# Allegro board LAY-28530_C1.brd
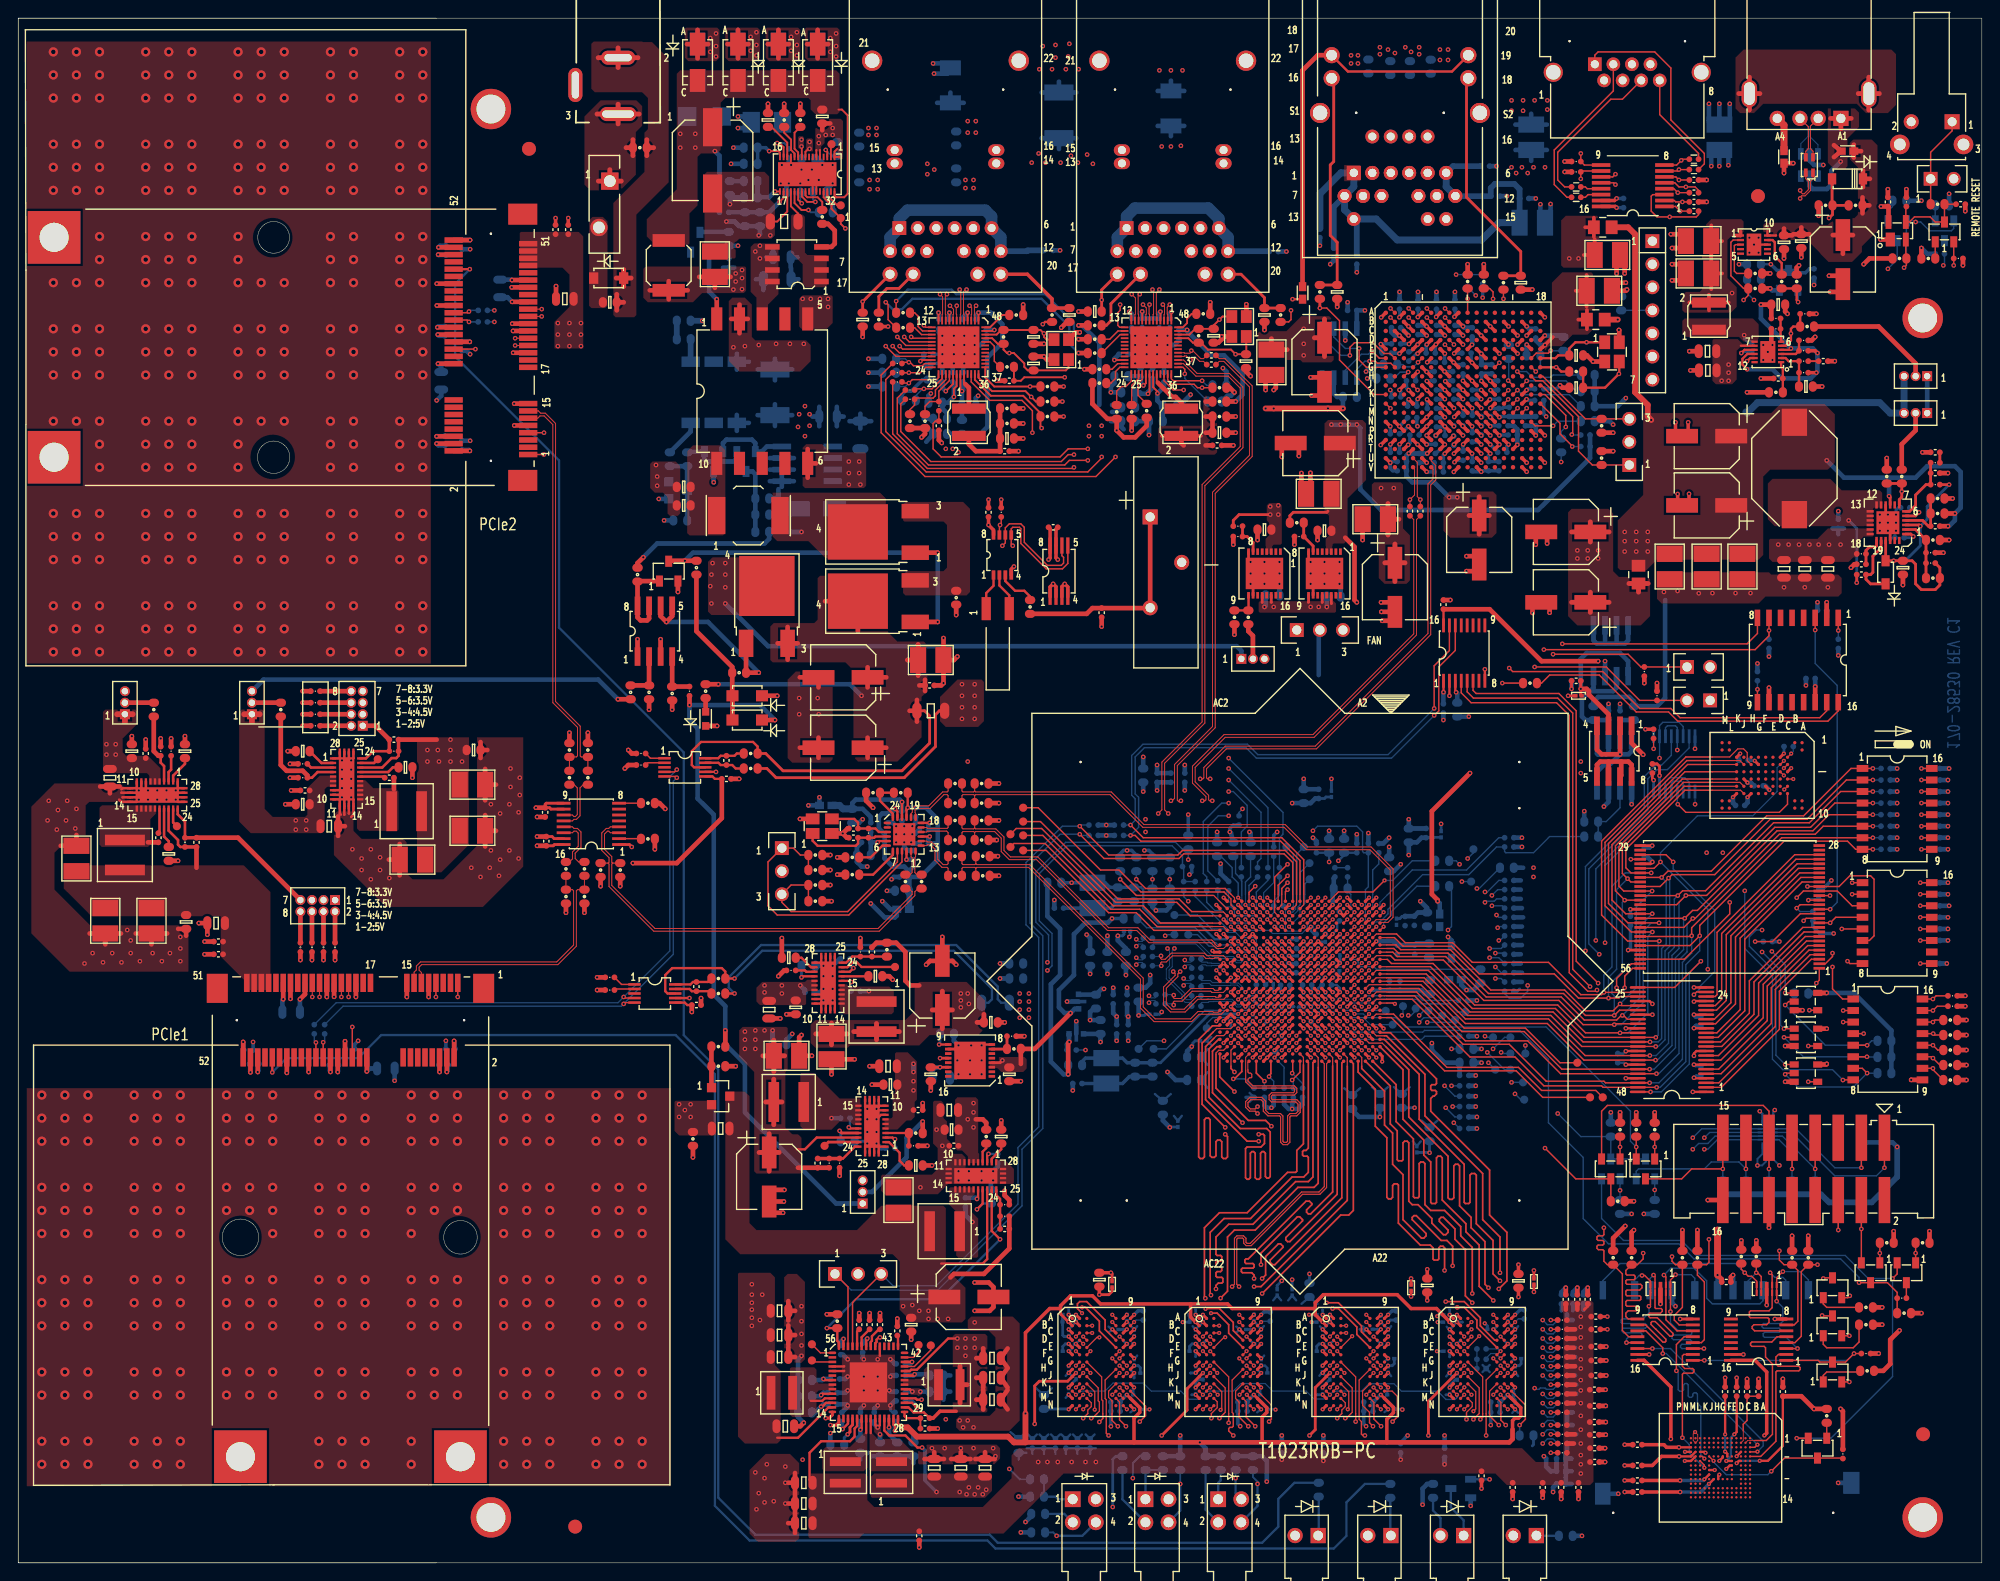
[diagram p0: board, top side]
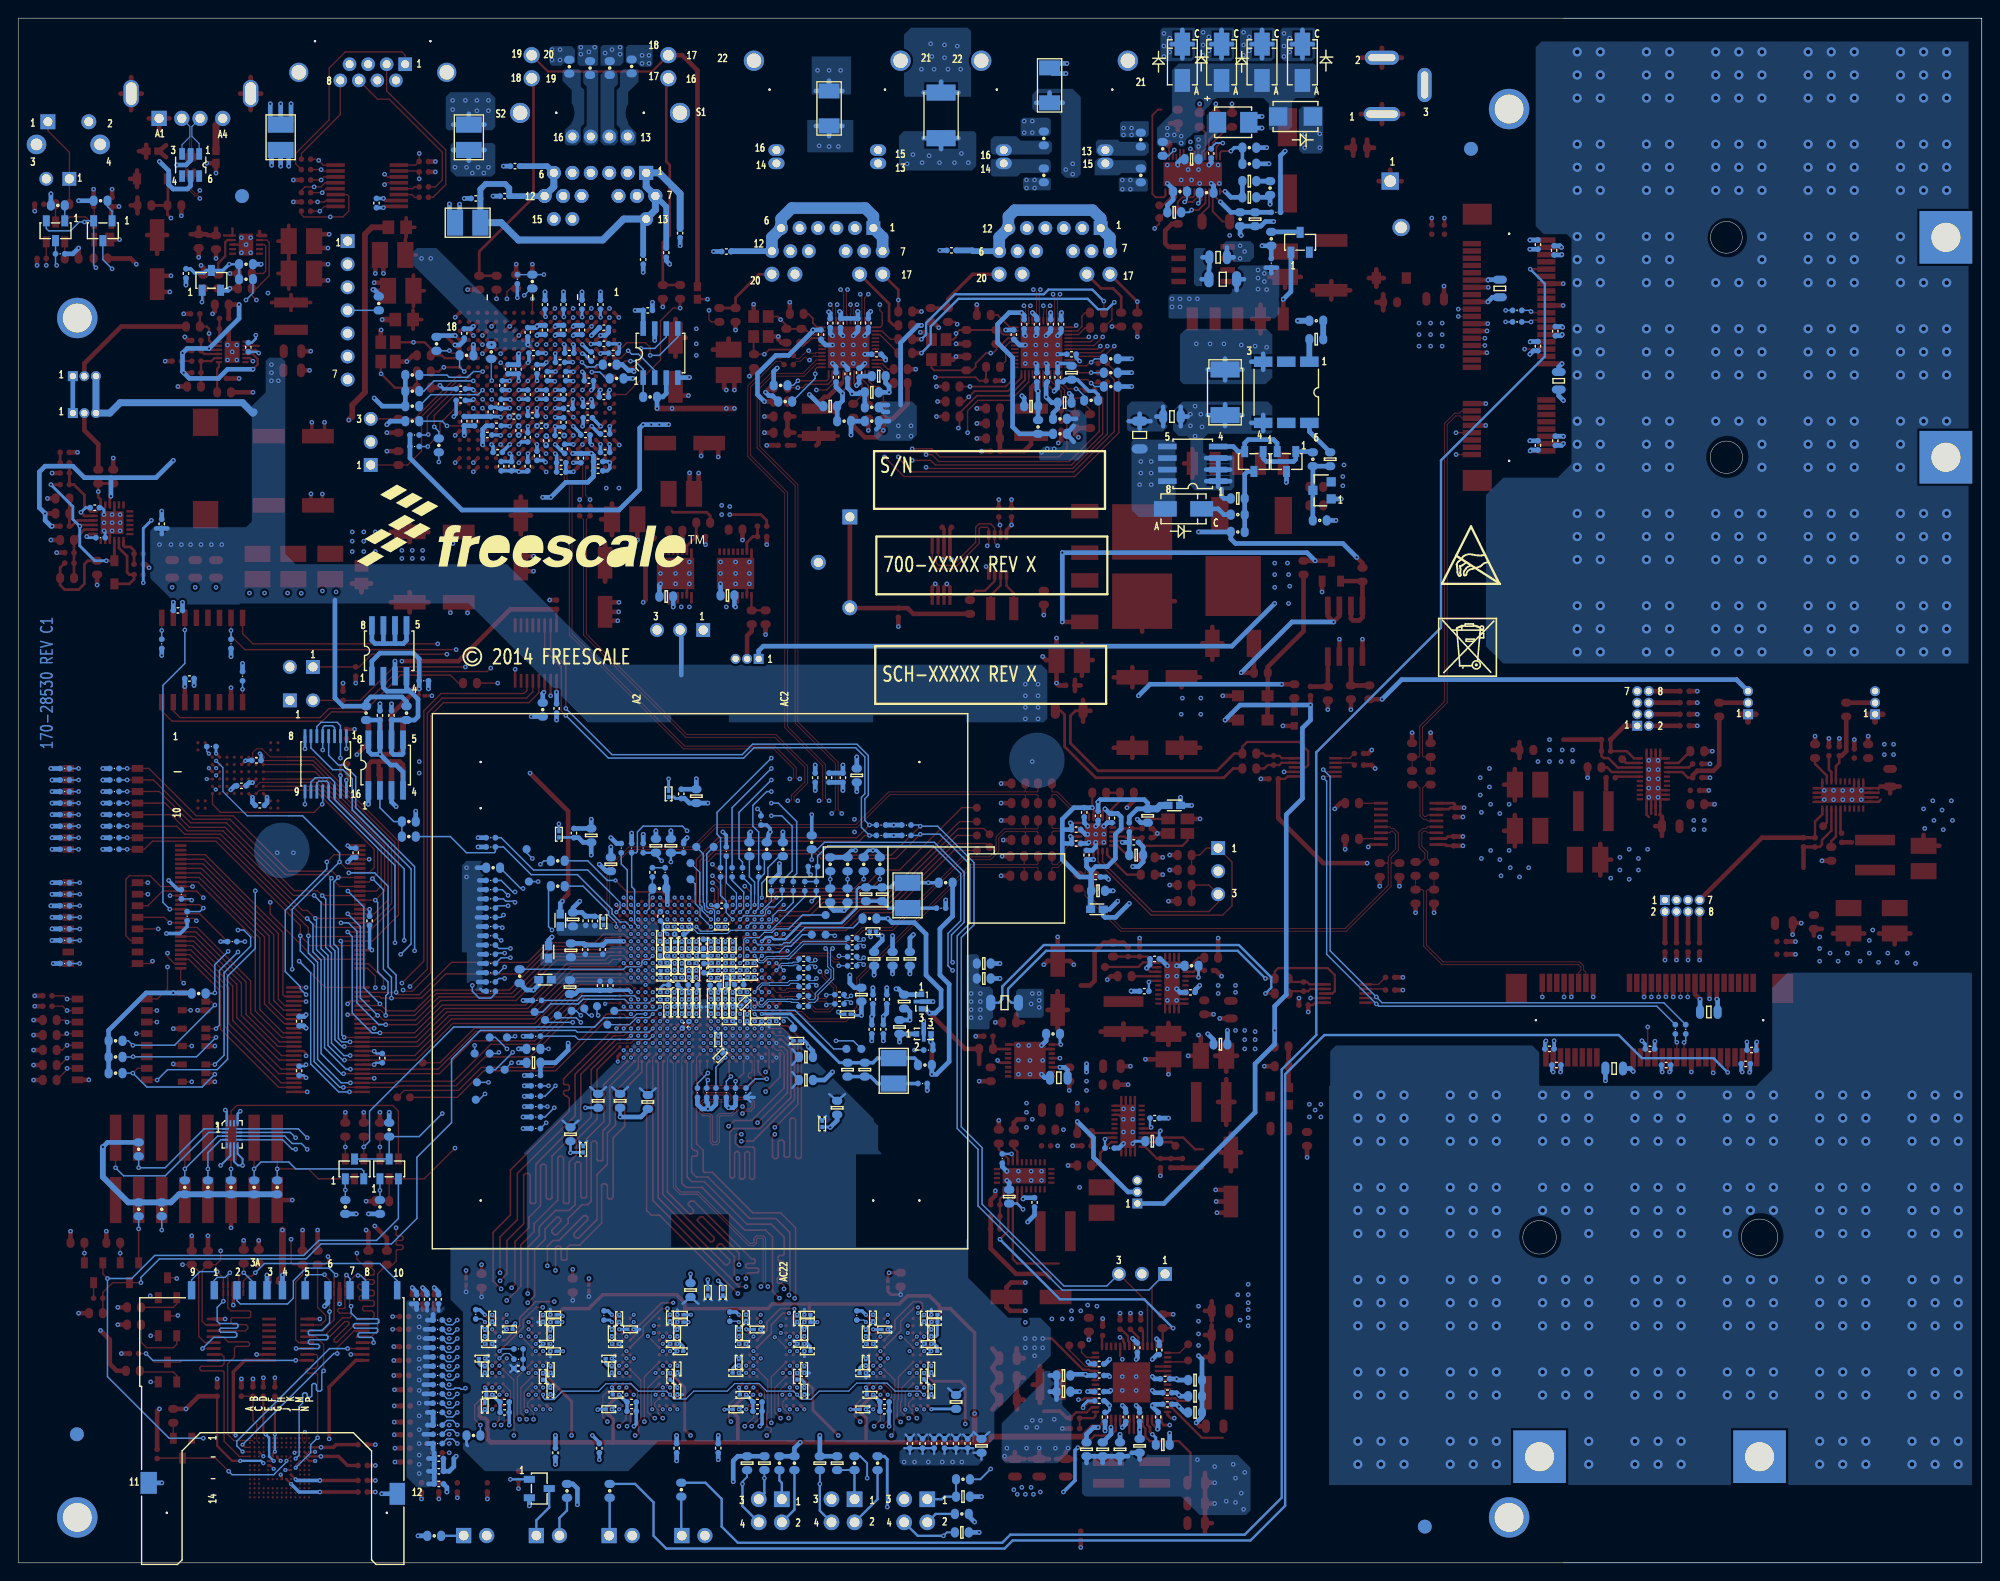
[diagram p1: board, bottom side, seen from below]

Outline 216 x 170 mm; copper layers: TOP, L2_GND, L3_INT1, L4_INT2, L5_PWR, BOTTOM. Coordinates in mm from the lower left corner of the outline.
Outline path: circle c24.45,35.83 r2 ; circle c28.1,145.88 r1.75 ; circle c28.1,121.68 r1.78 ; circle c48.65,35.83 r1.84 ; 0,170 0,0 216,0 216,170 46,170 ; 0,170 0,0 1,0 46,0 ; 0,170 1,170 46,170 ; 0,170 46,170

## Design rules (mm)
net group 2.5G-CMP: nets 2.5G_CMP_N 2.5G_CMP_P
net group 2.5GMDI0: nets 2.5G_MDI0_N 2.5G_MDI0_P
net group 2.5GMDI1: nets 2.5G_MDI1_N 2.5G_MDI1_P
net group 2.5GMDI3: nets 2.5G_MDI3_N 2.5G_MDI3_P
net group 2.5MDI2: nets 2.5G_MDI2_N 2.5G_MDI2_P
net group EC1--MDI2: nets EC1_MDIN2 EC1_MDIP2
net group EC1-MDI0: nets EC1_MDIN0 EC1_MDIP0
net group EC1-MDI1: nets EC1_MDIN1 EC1_MDIP1
net group EC1-MDI3: nets EC1_MDIN3 EC1_MDIP3
net group EC1_RXC: nets EC1_RXC EC1_RXC/PHYAD1
net group EC1_RXCTL: nets EC1_RXCTL EC1_RXCTL/PHYAD2
net group EC1_RXD1: nets EC1_RXD1 EC1_RXD1/CFG_MODE0
net group EC1_RXD2: nets EC1_RXD2 EC1_RXD2/CFG_MODE1
net group EC1_RXD3: nets EC1_RXD3 EC1_RXD3/CFG_MODE2
net group EC1_TXC: nets EC1_TXC N24320726
net group EC1_TXCTL: nets EC1_TXCTL N24320723
net group EC1_TXD0: nets EC1_TXD0 N24320797
net group EC1_TXD1: nets EC1_TXD1 N24320800
net group EC1_TXD2: nets EC1_TXD2 N24320803
net group EC1_TXD3: nets EC1_TXD3 N24320806
net group EC1_VDDREG: nets EC1_VDDREG N24288324
net group I2C1_SCL: nets I2C1_SCL N26621044
net group I2C1_SDA: nets I2C1_SDA N26621047
net group I2C2_SCL: nets I2C2_SCL N26620998
net group I2C2_SDA: nets I2C2_SDA N26621001
net group LANEA_RX_N: nets LANEA_RX_N N24582200
net group LANEA_RX_P: nets LANEA_RX_P N24582130
net group LANEA_TX_N: nets LANEA_TX_N N24582286
net group LANEA_TX_P: nets LANEA_TX_P N24582275
net group LANEB_RX_N: nets LANEB_RX_N N24582194
net group LANEB_RX_P: nets LANEB_RX_P N24582197
net group LANEB_TX_N: nets LANEB_TX_N N24185672
net group LANEB_TX_P: nets LANEB_TX_P N24185665
net group LANEC_RX_N: nets LANEC_RX_N N25115912
net group LANEC_RX_P: nets LANEC_RX_P N25115909
net group LANEC_TX_N: nets LANEC_TX_N N24582369
net group LANEC_TX_P: nets LANEC_TX_P N24582387
net group LANED_RX_N: nets LANED_RX_N N24307585
net group LANED_RX_P: nets LANED_RX_P N24307470
net group LANED_TX_N: nets LANED_TX_N N25116018
net group LANED_TX_P: nets LANED_TX_P N25116015
net group LED_G-: nets AQR_LED_GRN LED_G-
net group LED_Y-: nets AQR_LED_YEL LED_Y-
net group MPCIE1_CLK+: nets MPCIE1_CLK+ N24164587
net group MPCIE1_CLK-: nets MPCIE1_CLK- N24164590
net group MPCIE2_CLK+: nets MPCIE2_CLK+ N24164581
net group MPCIE2_CLK-: nets MPCIE2_CLK- N24164584
net group N23886021: nets N23886021 N23886023
net group N23886074: nets N23886069 N23886074
net group N24107203: nets N24107203 N24936812
net group N24107950: nets N24107950 N24108405
net group N24145679: nets N24145679 N24157795
net group N24145732: nets N24145732 N24145752
net group N24151368: nets N24151368 N24151377
net group N24158224: nets N24158107 N24158224
net group N24158233: nets N24158105 N24158233
net group N24187101: nets N24187101 N24616249
net group N24291582: nets N24291582 N24291591
net group N24302493: nets N24302493 N24302533
net group N24378650: nets N24378635 N24378650
net group N24379174: nets N24379174 N24380394
net group N24392141: nets N24392141 N25440106
net group N24480366: nets N24480366 N26683109
net group N24506911: nets N24506911 N24515056
net group N24509767: nets N24509767 N24509789
net group N24551325: nets N24551325 N24551347
net group N24994453: nets N24994453 N26682338
net group N25032157: nets N24389900 N25032157
net group N25157716: nets N25157716 N25157741
net group N25157815: nets N25157671 N25157815
net group N25169246: nets N24379631 N25169246
net group N26607524: nets N26607524 N26607860
net group N26607549: nets N26607549 N26607619
net group N26669831: nets N26669831 N26683821
net group N26901158: nets N26901158 N26901371
net group NUART_RTS: nets NUART_RTS RS232_RTS0
net group RS232_CTS0: nets NUART_CTS RS232_CTS0
net group RS232_RXD0: nets RS232_RXD0 UART_SIN
net group SD_CLK1_N: nets N24158001 SD_CLK1_N
net group SD_CLK1_P: nets N24158003 SD_CLK1_P
net group SD_CLK2_N: nets N24158103 SD_CLK2_N
net group SD_CLK2_P: nets N24158101 SD_CLK2_P
net group SDHC_VS: nets N24675233 SDHC_VS
net group SGMII-MDI0: nets SGMII_MDIN0 SGMII_MDIP0
net group SGMII-MDI1: nets SGMII_MDIN1 SGMII_MDIP1
net group SGMII-MDI2: nets SGMII_MDIN2 SGMII_MDIP2
net group SGMII-MDI3: nets SGMII_MDIN3 SGMII_MDIP3
net group SYS_REFCLK_N: nets N24157991 SYS_REFCLK_N
net group SYS_REFCLK_P: nets N24157984 SYS_REFCLK_P
net group UART_SOUT: nets RS232_TXD0 UART_SOUT
net group USB1: nets N24378208 N24378216
net group USB2: nets N24378188 N24378195
net group VBAT_OPT1: nets N23887688 VBAT_OPT1
net group VR500_1V5: nets N24081686 VR500_1V5
net group 12: nets 12 N26747839 N26748165
net group 12V_DECT: nets 12V_DECT N24653996 N24678302 N25120670
net group 12V_SUP: nets 12V_SUP N24652945 N24654004
net group 34: nets 34 N26747836 N26748168
net group 56: nets 56 N26747833 N26748171
net group 78: nets 78 N26747830 N26748174
net group ADP_12V: nets ADP_12V N25696806 N26711184 N26711194
net group AQR_INT_N: nets 1V2_RST_N AQR105_VA12 AQR_INT_N EMI2_MDC EMI2_MDIO N24186507 N24186703 N24189801 N24970769
net group AVDD_SD1_PLL1: nets AVDD_SD1_PLL1 N24275030 N24275210 N24275332 N24275468 N24443017
net group DCDC_1V0_SUP: nets DCDC_1V0_SUP N24137912 N24137946 N24137962 N25622344 N25622365
net group DCDC_5V0: nets DCDC_5V0 N24480273 N24480391
net group DDR-DATA1-U1-U37: nets DDR4_DM0 DDR4_DQ0 DDR4_DQ1 DDR4_DQ2 DDR4_DQ3 DDR4_DQ4 DDR4_DQ5 DDR4_DQ6 DDR4_DQ7 DDR4_DQS0 DDR4_DQS0_N
net group DDR-DATA3-U1-U35: nets DDR4_DM2 DDR4_DQ16 DDR4_DQ17 DDR4_DQ18 DDR4_DQ19 DDR4_DQ20 DDR4_DQ21 DDR4_DQ22 DDR4_DQ23 DDR4_DQS2 DDR4_DQS2_N
net group DDR-DATA4-U1-U34: nets DDR4_DM3 DDR4_DQ24 DDR4_DQ25 DDR4_DQ26 DDR4_DQ27 DDR4_DQ28 DDR4_DQ29 DDR4_DQ30 DDR4_DQ31 DDR4_DQS3 DDR4_DQS3_N
net group DDR-DATA-UI-U36: nets DDR4_DM1 DDR4_DQ8 DDR4_DQ9 DDR4_DQ10 DDR4_DQ11 DDR4_DQ12 DDR4_DQ13 DDR4_DQ14 DDR4_DQ15 DDR4_DQS1 DDR4_DQS1_N
net group EC1_AVDD10: nets EC1_AVDD10 EC1_DVDD10 N24289313 N24289334
net group EC1_DVDD_3V3: nets EC1_DVDD_3V3 EC1_LED0/PHYAD0 EC1_LED2/CFG_LDO1 N25236971
net group EC1_DVDDRG: nets EC1_DVDDRG EC1_RXD0 N24291955
net group EC1_LED1/CFG_LDO0: nets EC1_LED1/CFG_LDO0 N24294558 N25235874
net group EMI1_MDC: nets EMI1_MDC N25171285 N25171337
net group EMI1_MDIO: nets EMI1_MDIO N25171340 N25276538
net group GND_SIGNAL: nets GND_SIGNAL N24105172 N24105186 N24105908 N24106035 N24106207 N24106733 N24106981 N24107357 N24108952 N24109652 N24109671 N24109742 N24109897 N24109974 N24109983 N24110294 N24932777 N24935123 N24935830 N24935853 N25029315
net group GPIO3_0_WAKE_L: nets GPIO3_0_WAKE_L N26623758 N26628373
net group INTVCC: nets INTVCC N25157944 N25158030 N25158044
net group LDO_1V0: nets LDO_1V0 N24442993 N25212963
net group N24107483: nets N24107470 N24107483 N24107486
net group N24107780: nets N24107616 N24107621 N24107780
net group N24379558: nets N24378377 N24379468 N24379558
net group N24480234: nets N24480234 N24480259 N24480399 N24480593 N24480595
net group POE_12V: nets N24107840 N24107947 N24108768 N25118599 POE_12V
net group SGMII_AVDD10: nets N24302177 N24302183 SGMII_AVDD10 SGMII_DVDD10
net group SGMII_DVDD_3V3: nets DCDC1_3V3 N24301989 N24506783 N24506809 N24506829 N25238664 SGMII_DVDD_3V3 SGMII_LED0/PHYAD0 SGMII_LED2/CFG_LDO1 SGMII_VDDREG
net group SGMII_DVDDRG: nets SGMII_DVDDRG SGMII_RXC/PHYAD1 SGMII_RXD1/CFG_MODE0 SGMII_RXD2/CFG_MODE1
net group SGMII_LED1/CFG_LDO0: nets N24303062 N25239505 SGMII_LED1/CFG_LDO0
net group VPA: nets N26669717 N26669739 N26669755 VPA
net group VPA_PCIE2: nets N26901046 N26901068 N26901080 VPA_PCIE2

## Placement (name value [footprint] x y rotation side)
BH1  Mounting Hole  [MH175-125P]  52 160 0 top
BH2  Mounting Hole  [MH175-125P]  209.5 137 0 top
BH3  Mounting Hole  [MH175-125P]  52 5 0 top
BH4  Mounting Hole  [MH175-125P]  209.5 5 0 top
BT1  WBA-3B2 U  [SKT_BAT_225X886_3V]  124.52 115.11 270 top
C1  0.1uF  [CC0603_OV]  88.45 159.18 270 top
C2  10uF  [CASE_F_8P5X8P5]  76.38 154.35 270 top
C3  0.1uF  [CC0402_25]  184.33 152.19 0 top
C4  0.1uF  [CC0402_25]  184.33 150.8 180 top
C5  0.1uF  [CC0402_25]  184.33 149.78 0 top
C6  0.1uF  [CC0402_25]  205.67 149.78 90 top
C7  0.1uF  [CC0402_25]  213.67 149.53 180 top
C8  0.1uF  [CC0402_25]  184.33 148.77 0 top
C9  100PF  [CC0603_OV]  65.08 138.73 0 top
C10  47UF  [CC1210]  184.84 145.46 180 top
C11  1000PF  [CC0603_OV]  196.14 145.46 270 top
C12  10uF  [CC0603_OV]  194.24 145.34 270 top
C13  47UF  [CC1210]  174.81 143.94 0 top
C14  100uF  [CCE63X55]  200.72 143.43 270 top
C15  47UF  [CC1210]  184.84 141.91 180 top
C16  470PF  [CC0603_OV]  165.28 140.89 270 top
C17  47UF  [CC1210]  173.92 140 0 top
C18  470PF  [CC0603_OV]  145.09 139.88 270 top
C19  4.7uF  [CC0603_OV]  193.6 138.48 180 top
C20  100PF  [CC0603_OV]  118.42 137.72 180 top
C21  2200PF  [CC1812_A]  83.24 128.83 270 bottom
C22  100PF  [CC0603_OV]  115.63 137.34 270 top
C23  100PF  [CC0603_OV]  137.09 137.34 270 top
C24  100PF  [CC0603_OV]  92.89 136.83 270 top
C25  18PF  [CC0603_OV]  131.5 135.05 270 top
C26  18PF  [CC0603_OV]  111.69 134.92 270 top
C27  470pF  [CC0805_OV]  89.08 126.16 180 bottom
C28  4.7uF  [CC0603_OV]  73.21 118.41 180 top
C29  22uF  [CC0805_OV]  185.83 133.35 180 top
C30  0.1uF  [CC0402_25]  131.25 132.89 180 top
C31  18PF  [CC0603_OV]  171.38 132.89 0 top
C32  68PF  [CC0402_25]  198.56 132.26 180 top
C33  18PF  [CC0603_OV]  135.06 132.26 270 top
C34  47UF  [CC1210]  137.85 132.13 270 top
C35  100uF  [CCE63X55]  143.69 132.13 270 top
C36  18PF  [CC0603_OV]  111.69 132 90 top
C37  0.1uF  [CC0402_25]  131.25 131.87 180 top
C38  4.7uF  [CC0603_OV]  73.21 116.38 180 top
C39  22uF  [CC0805_OV]  185.86 131.24 180 top
C40  1UF  [CC0603_OV]  81.84 117.14 0 bottom
C41  0.1uF  [CC0402_25]  193.6 130.35 180 top
C42  22PF  [CC0402_25]  109.02 130.1 180 top
C43  10PF  [CC0603_OV]  196.65 129.46 180 top
C44  18PF  [CC0603_OV]  171.38 129.33 180 top
C45  22PF  [CC0402_25]  101.28 125.14 270 top
C46  4.7uF  [CC0603_OV]  132.14 124.38 0 top
C47  100uF  [CCE63X55]  185.73 124 180 top
C48  4.7uF  [CC0603_OV]  108.77 123.75 0 top
C49  100uF  [CCE63X55]  142.68 123.24 180 top
C50  0.1uF  [CC0402_25]  131.88 122.98 180 top
C51  0.1uF  [CC0402_25]  108.51 122.35 180 top
C52  220pF  [CC0402_25]  210.88 122.22 180 top
C53  10pF  [CC0402_25]  210.88 119.94 0 top
C54  47UF  [CC1210]  143.06 117.65 180 top
C55  100uF  [CCE63X55]  185.73 116.38 180 top
C56  0.1uF  [CC0402_25]  153.09 115.75 90 top
C57  0.1uF  [CC0402_25]  154.23 115.75 90 top
C58  47UF  [CC1210]  149.28 114.86 180 top
C59  100UF  [CCE63X55]  90.73 97.46 180 top
C60  0.1uF  [CC0402_25]  119.18 104.57 270 top
C61  100PF  [CC0402_25]  210.88 114.09 180 top
C62  10uF  [CC0603_OV]  137.09 113.71 180 top
C63  10uF  [CC0603_OV]  143.69 113.59 180 top
C64  100uF  [CCE63X55]  170.24 113.46 180 top
C65  100uF  [CCE63X55]  160.71 112.57 270 top
C66  0.1uF  [CC0402_25]  106.74 115.62 90 top
C67  0.1uF  [CC0402_25]  202.75 109.9 180 top
C68  47UF  [CC1210]  181.67 109.65 270 top
C69  47UF  [CC1210]  185.73 109.65 270 top
C70  47UF  [CC1210]  189.67 109.65 270 top
C71  2.2uF  [CC0603_OV]  207.32 109.52 270 top
C72  22uF  [CC0805_OV]  194.24 109.4 270 top
C73  22uF  [CC0805_OV]  196.53 109.4 270 top
C74  22uF  [CC0805_OV]  199.07 109.4 270 top
C75  0.1uF  [CC0402_25]  202.75 108.76 0 top
C76  100uF  [CCE63X55]  151.44 107.36 270 top
C77  100UF  [CCE63X55]  90.73 89.71 180 top
C78  100uF  [CCE63X55]  170.24 105.71 180 top
C79  22UF  [CC1210]  100.39 99.36 0 top
C80  0.1uF  [CC0402_25]  100.26 96.57 0 top
C81  0.01UF  [CC0402_25]  171.38 97.08 180 top
C82  0.1UF  [CC0201]  171.63 95.43 180 top
C84  0.1uF  [CC0402_25]  77.91 86.28 180 top
C85  2pF  [CC0402_25]  91.88 80.82 180 top
C86  2pF  [CC0402_25]  91.88 79.8 180 top
C87  10pF  [CC0402_25]  93.91 67.23 270 top
C88  2200PF  [CC0603_OV]  84.77 66.6 180 top
C89  1UF  [CC0603_OV]  94.29 64.56 0 top
C90  100uF  [CCE63X55]  101.66 63.55 90 top
C91  10uF  [CC0603_OV]  85.53 61.14 270 top
C92  22uF  [CC0805_OV]  82.61 60.88 270 top
C93  1UF  [CC0603_OV]  106.99 59.48 0 top
C94  47UF  [CC1210]  89.46 56.82 270 top
C95  47UF  [CC1210]  84.51 55.8 0 top
C96  22uF  [CC0805_OV]  95.69 54.66 180 top
C97  10uF  [CC0603_OV]  100.39 53.77 270 top
C98  10uF  [CC0603_OV]  109.02 53.77 270 top
C99  10uF  [CC0603_OV]  95.94 52.63 180 top
C100  0.1uF  [CC0402_25]  98.99 49.83 180 top
C101  22uF  [CC0805_OV]  102.42 49.83 180 top
C102  10uF  [CC0603_OV]  102.67 47.67 180 top
C103  2200PF  [CC0603_OV]  108.13 46.91 90 top
C104  0.1uF  [CC0402_25]  102.93 45.9 0 top
C105  2200PF  [CC0603_OV]  98.74 43.74 0 top
C106  10pF  [CC0402_25]  87.94 43.99 90 top
C107  100uF  [CCE63X55]  82.61 42.47 270 top
C108  47UF  [CC1210]  96.83 39.93 90 top
C109  10pF  [CC0402_25]  108.51 36.75 180 top
C110  10uF  [CC0603_OV]  118.93 31.16 90 top
C111  10uF  [CC0603_OV]  165.03 31.04 90 top
C112  0.1UF  [CC0201]  166.73 30.96 90 top
C113  0.1uF  [CC0402_25]  187.89 30.91 0 top
C114  0.1UF  [CC0201]  120.33 30.66 90 top
C115  10uF  [CC0603_OV]  155 30.53 90 top
C116  22UF  [CC0805_OV]  84.38 15.03 0 top
C117  0.1UF  [CC0201]  153.22 30.27 90 top
C118  100uF  [CCE63X55]  104.58 29.26 0 top
C119  0.1uF  [CC0402_25]  170.24 29 90 top
C120  0.1uF  [CC0402_25]  171.51 29 90 top
C121  0.1uF  [CC0402_25]  172.65 29 90 top
C122  22UF  [CC0805_OV]  83.75 27.73 0 top
C123  0.1uF  [CC0402_25]  173.54 27.1 0 top
C124  0.22UF  [CC0402_25]  92.51 26.21 90 top
C125  1.0UF  [CC0402_25]  93.66 26.21 90 top
C126  1.0UF  [CC0402_25]  94.8 26.21 90 top
C127  1UF  [CC0603_OV]  98.23 26.21 270 top
C128  0.1uF  [CC0402_25]  173.54 25.7 0 top
C129  0.47uF  [CC0402_25]  96.7 25.52 90 top
C130  22UF  [CC0805_OV]  83.75 25.07 0 top
C131  0.1uF  [CC0402_25]  173.54 23.8 0 top
C132  22UF  [CC0805_OV]  83.75 22.65 0 top
C133  22UF  [CC0805_OV]  107.12 22.53 0 top
C134  0.1uF  [CC0402_25]  173.54 22.27 0 top
C135  0.1uF  [CC0402_25]  173.54 20.62 0 top
C136  22UF  [CC0805_OV]  107.12 20.37 0 top
C137  0.1uF  [CC0402_25]  173.38 19.05 0 top
C138  0.1uF  [CC0402_25]  187.76 18.84 90 top
C139  0.1uF  [CC0402_25]  189.03 18.84 90 top
C140  0.1uF  [CC0402_25]  190.18 18.84 90 top
C141  1UF  [CC0402_25]  191.45 18.84 90 top
C142  2.2uF  [CC0402_25]  194.11 18.84 270 top
C143  22UF  [CC0805_OV]  107.12 17.96 0 top
C144  0.1uF  [CC0402_25]  173.38 17.27 0 top
C145  0.1UF  [CC0402_25]  99.75 15.92 180 top
C146  0.1uF  [CC0402_25]  173.38 15.49 0 top
C147  0.1UF  [CC0402_25]  99.75 14.78 0 top
C148  0.1uF  [CC0402_25]  173.38 14.1 0 top
C149  1UF  [CC0402_25]  178.11 13 180 top
C150  0.1uF  [CC0402_25]  173.41 12.62 0 top
C151  0.1uF  [CC0402_25]  173.41 11.1 0 top
C152  0.1uF  [CC0402_25]  178.11 10.72 180 top
C153  22UF  [CC0805_OV]  100.77 10.46 90 top
C154  22UF  [CC0805_OV]  103.69 10.46 90 top
C155  22UF  [CC0805_OV]  106.36 10.46 90 top
C156  0.1uF  [CC0402_25]  160.97 9.57 270 top
C157  0.1uF  [CC0402_25]  178.11 9.07 180 top
C158  22UF  [CC0805_OV]  86.42 8.81 180 top
C159  0.1uF  [CC0402_25]  164.39 8.3 270 top
C160  0.1uF  [CC0402_25]  167.7 8.3 270 top
C161  0.1uF  [CC0402_25]  169.73 8.3 270 top
C162  0.1uF  [CC0402_25]  171.63 8.3 270 top
C163  2.2uF  [CC0402_25]  178.11 7.8 0 top
C164  22UF  [CC0805_OV]  86.42 6.53 180 top
C165  22UF  [CC0805_OV]  86.42 4.37 180 top
C166  0.1uF  [CC0402_25]  99.12 2.97 270 top
C167  1000pF  [CC1808_A]  102.55 162.61 90 bottom
C168  1000pF  [CC1808_A]  126.8 160.07 90 bottom
C169  0.1uF  [CC1812]  114.48 159.31 90 bottom
C170  22uF  [CC3528-21]  82.35 158.54 180 bottom
C171  1000pf  [CC1210]  187.13 156.89 90 bottom
C172  1000pf  [CC1210]  166.43 156.89 90 bottom
C173  33PF  [CC0402_25]  84.77 155.12 270 bottom
C174  33PF  [CC0603_OV]  82.48 158.8 90 top
C175  1UF  [CC0603_OV]  86.92 154.48 0 bottom
C176  2.2uF  [CC0402_25]  161.35 153.72 180 bottom
C177  4700PF  [CC0603_OV]  80.57 152.07 0 bottom
C178  1000PF  [CC0603_OV]  80.57 150.29 0 bottom
C179  2.2uF  [CC0402_25]  162.49 150.42 180 bottom
C180  620pF  [CC0402_25]  165.66 150.16 0 bottom
C181  1UF  [CC0603_OV]  79.94 147.88 270 bottom
C182  0.1uF  [CC0402_25]  176.59 149.65 270 bottom
C183  2.2uF  [CC1210]  76.64 142.92 90 top
C184  0.1uF  [CC0603_OV]  88.83 148.64 0 bottom
C185  47UF  [CC1210]  166.55 147.5 0 bottom
C186  47pF  [CC0805_OV]  84 143.69 180 bottom
C187  2.2uF  [CC0402_25]  143.19 146.35 90 bottom
C188  1UF  [CC0603_OV]  73.21 134.67 0 bottom
C189  0.01UF  [CC0402_25]  113.34 144.45 0 bottom
C190  0.01UF  [CC0402_25]  138.11 144.32 0 bottom
C191  2.2uF  [CC0402_25]  144.71 144.19 90 bottom
C192  2.2uF  [CC0402_25]  147.25 143.43 90 bottom
C193  0.1uF  [CC0402_25]  197.54 141.91 90 bottom
C194  2.2uF  [CC0402_25]  158.04 138.48 270 bottom
C195  2.2uF  [CC0402_25]  156.01 138.48 270 bottom
C196  2.2uF  [CC0402_25]  153.98 138.48 270 bottom
C197  2.2uF  [CC0402_25]  151.95 138.48 270 bottom
C198  1UF  [CC0402_25]  146.74 137.84 180 bottom
C199  0.1uF  [CC0402_25]  125.53 136.45 90 bottom
C200  0.1uF  [CC0402_25]  123.63 136.45 90 bottom
C201  0.1uF  [CC0402_25]  122.48 136.45 90 bottom
C202  0.1uF  [CC0402_25]  126.68 136.45 90 bottom
C203  0.1uF  [CC0402_25]  105.34 136.32 90 bottom
C204  0.1uF  [CC0402_25]  103.94 136.32 90 bottom
C205  0.1uF  [CC0402_25]  102.42 136.32 90 bottom
C206  0.1uF  [CC0402_25]  101.28 136.32 90 bottom
C207  2.2uF  [CC0402_25]  151.57 135.94 0 bottom
C208  2200PF  [CC0603_OV]  71.68 121.46 270 bottom
C209  2.2uF  [CC0402_25]  158.04 135.68 270 bottom
C210  2.2uF  [CC0402_25]  156.01 135.68 270 bottom
C211  2.2uF  [CC0402_25]  153.98 135.68 270 bottom
C212  2.2uF  [CC0402_25]  159.95 135.43 270 bottom
C213  2.2uF  [CC0402_25]  166.93 135.3 270 bottom
C214  0.1uF  [CC0402_25]  127.69 135.18 90 bottom
C215  0.1uF  [CC0402_25]  106.48 135.18 90 bottom
C216  2.2uF  [CC0402_25]  151.57 134.16 0 bottom
C217  0.1uF  [CC0402_25]  190.68 133.78 270 bottom
C218  0.1uF  [CC0402_25]  150.55 133.14 0 bottom
C219  2.2uF  [CC0402_25]  159.31 133.14 180 bottom
C220  2.2uF  [CC0402_25]  155.38 133.14 180 bottom
C221  0.1uF  [CC0402_25]  121.6 133.02 180 bottom
C222  0.1uF  [CC0402_25]  100.13 133.02 180 bottom
C223  2.2uF  [CC0402_25]  152.96 132.76 270 bottom
C224  2.2uF  [CC0402_25]  156.39 132.13 0 bottom
C225  2.2uF  [CC0402_25]  162.11 131.37 270 bottom
C226  2.2uF  [CC0402_25]  160.97 131.37 270 bottom
C227  2.2uF  [CC0402_25]  158.93 131.37 270 bottom
C228  0.1uF  [CC0402_25]  123.5 130.99 270 bottom
C229  4.7uF  [CC0603_OV]  100.13 130.99 90 bottom
C230  0.1uF  [CC0402_25]  124.77 130.86 270 bottom
C231  2.2uF  [CC0402_25]  157.79 130.6 270 bottom
C232  2.2uF  [CC0402_25]  155.76 130.6 270 bottom
C233  4.7uF  [CC0603_OV]  121.34 130.6 180 bottom
C234  0.1uF  [CC0402_25]  126.04 130.48 270 bottom
C235  0.1uF  [CC0402_25]  103.94 130.48 270 bottom
C236  0.1uF  [CC0402_25]  102.8 130.48 270 bottom
C237  0.1uF  [CC0402_25]  101.66 130.48 270 bottom
C238  0.1uF  [CC0402_25]  153.22 130.1 180 bottom
C239  2.2uF  [CC0402_25]  162.74 129.59 270 bottom
C240  0.1uF  [CC0402_25]  167.32 129.21 180 bottom
C241  4.7uF  [CC0603_OV]  122.1 128.83 180 bottom
C242  2.2uF  [CC0402_25]  159.95 128.57 270 bottom
C243  2.2uF  [CC0402_25]  157.92 128.57 270 bottom
C244  2.2uF  [CC0402_25]  156.01 128.57 270 bottom
C245  0.1uF  [CC0402_25]  151.57 128.32 0 bottom
C246  0.1uF  [CC0402_25]  167.32 127.94 180 bottom
C247  4.7uF  [CC0603_OV]  100.89 127.68 180 bottom
C248  2.2uF  [CC0402_25]  162.87 127.56 90 bottom
C249  2.2uF  [CC0402_25]  153.35 127.3 0 bottom
C250  4.7uF  [CC0603_OV]  126.68 127.3 0 bottom
C251  4.7uF  [CC0603_OV]  104.58 127.3 0 bottom
C252  2.2uF  [CC0402_25]  155.5 127.05 180 bottom
C253  2.2uF  [CC0402_25]  164.01 126.67 270 bottom
C254  2.2uF  [CC0402_25]  159.44 126.29 0 bottom
C255  2.2uF  [CC0402_25]  161.47 126.16 180 bottom
C256  2.2uF  [CC0402_25]  153.35 126.03 0 bottom
C257  2.2uF  [CC0402_25]  166.93 125.65 90 bottom
C258  2.2uF  [CC0402_25]  165.79 125.65 90 bottom
C259  2.2uF  [CC0402_25]  156.01 125.52 90 bottom
C260  2.2uF  [CC0402_25]  163.38 125.14 180 bottom
C261  2.2uF  [CC0402_25]  158.43 125.14 180 bottom
C262  2.2uF  [CC0402_25]  160.97 124.64 270 bottom
C263  2.2uF  [CC0402_25]  151.44 124.25 0 bottom
C264  2.2uF  [CC0402_25]  164.39 124.13 180 bottom
C265  2.2uF  [CC0402_25]  153.6 124.13 0 bottom
C266  2.2uF  [CC0402_25]  156.44 124.08 180 bottom
C267  2.2uF  [CC0402_25]  159.95 123.87 90 bottom
C268  2.2uF  [CC0402_25]  157.92 123.49 90 bottom
C269  0.01UF  [CC0402_25]  155.89 122.6 270 bottom
C270  2.2uF  [CC0402_25]  163.25 122.22 180 bottom
C271  2.2uF  [CC0402_25]  151.44 122.22 0 bottom
C272  2.2uF  [CC0402_25]  158.93 121.84 90 bottom
C273  0.01UF  [CC0402_25]  154.11 121.59 270 bottom
C274  0.01UF  [CC0402_25]  152.2 121.21 180 bottom
C275  0.01UF  [CC0402_25]  156.27 121.08 180 bottom
C276  0.1uF  [CC0402_25]  162.87 120.7 90 bottom
C277  0.01UF  [CC0402_25]  161.73 120.7 270 bottom
C278  0.01UF  [CC0402_25]  159.95 120.7 270 bottom
C279  0.1uF  [CC0402_25]  152.2 120.19 0 bottom
C280  0.1uF  [CC0402_25]  156.27 120.06 0 bottom
C281  0.1uF  [CC0402_25]  207.57 116.13 180 bottom
C282  0.1uF  [CC0402_25]  200.21 114.35 90 bottom
C283  10uF  [CC0603_OV]  137.98 106.47 0 bottom
C284  10uF  [CC0603_OV]  144.71 106.35 0 bottom
C285  0.1uF  [CC0402_25]  198.43 104.82 180 bottom
C286  0.1uF  [CC0402_25]  113.85 113.97 0 top
C287  0.1uF  [CC0402_25]  197.16 97.33 180 bottom
C288  0.01UF  [CC0402_25]  176.21 93.27 270 bottom
C289  0.01UF  [CC0402_25]  174.94 93.27 270 bottom
C290  0.1uF  [CC0402_25]  189.79 88.31 180 bottom
C292  10uF  [CC0603_OV]  123.75 86.66 90 bottom
C293  0.01UF  [CC0402_25]  128.33 86.41 90 bottom
C294  0.1uF  [CC0402_25]  126.8 86.41 90 bottom
C295  0.1uF  [CC0402_25]  125.28 86.41 90 bottom
C296  0.1uF  [CC0402_25]  191.45 85.52 0 bottom
C297  0.1UF  [CC0201]  144.46 84.63 90 bottom
C298  0.01UF  [CC0402_25]  143.06 84.63 90 bottom
C299  10uF  [CC0603_OV]  141.41 84.38 90 bottom
C300  22UF  [CC0805_OV]  30.03 60.63 0 bottom
C301  0.1uF  [CC0402_25]  189.41 83.36 180 bottom
C302  0.1uF  [CC0402_25]  98.74 82.6 270 bottom
C303  0.1uF  [CC0402_25]  97.21 82.22 270 bottom
C304  10uF  [CC0603_OV]  91.75 82.22 270 bottom
C305  0.1uF  [CC0402_25]  95.69 81.96 270 bottom
C306  0.1uF  [CC0402_25]  36.51 56.56 0 bottom
C307  0.1uF  [CC0402_25]  25.33 56.44 0 bottom
C308  0.1uF  [CC0402_25]  47.55 56.56 180 bottom
C309  0.1uF  [CC0402_25]  99.62 80.69 180 bottom
C310  0.01UF  [CC0402_25]  154.87 80.31 90 bottom
C311  0.01uF  [CC0201]  156.52 80.19 90 bottom
C312  10uF  [CC0603_OV]  152.96 80.06 90 bottom
C313  0.1uF  [CC0402_25]  93.27 79.3 180 bottom
C314  0.1uF  [CC0402_25]  99.62 79.17 180 bottom
C315  10uF  [CC0603_OV]  145.85 78.92 90 bottom
C316  10uF  [CC0603_OV]  144.2 78.92 90 bottom
C317  0.1uF  [CC0402_25]  178.87 78.15 270 bottom
C318  0.1uF  [CC0402_25]  98.48 77.9 90 bottom
C319  10uF  [CC0603_OV]  93.02 77.9 180 bottom
C320  10uF  [CC0603_OV]  150.81 76.88 270 bottom
C321  0.1uF  [CC0402_25]  46.79 54.79 0 bottom
C322  0.1uF  [CC0402_25]  34.73 54.79 0 bottom
C323  0.1uF  [CC0402_25]  146.23 75.99 90 bottom
C324  0.1uF  [CC0402_25]  25.96 54.91 180 bottom
C325  0.1uF  [CC0402_25]  97.47 75.49 180 bottom
C326  22UF  [CC0805_OV]  40.44 54.4 180 bottom
C327  10uF  [CC0603_OV]  97.21 73.96 180 bottom
C328  3000pF  [CC0603_OV]  122.74 73.58 270 bottom
C329  4.7uF  [CC0603_OV]  120.96 73.58 270 bottom
C330  47UF  [CC1210]  118.17 73.45 270 bottom
C331  22PF  [CC0402_25]  138.61 72.31 0 bottom
C332  0.1uF  [CC0402_25]  177.35 70.66 270 bottom
C333  1UF  [CC0402_25]  145.34 71.17 90 bottom
C334  3000pF  [CC0603_OV]  154.97 70.81 90 bottom
C335  2.2uF  [CC0402_25]  153.57 70.66 270 bottom
C336  2.2uF  [CC0402_25]  152.56 70.63 270 bottom
C337  0.1UF  [CC0201]  151.62 70.56 90 bottom
C338  0.1UF  [CC0201]  144.23 70.03 180 bottom
C339  0.1UF  [CC0201]  138.61 70.03 180 bottom
C340  0.1UF  [CC0201]  142.63 70 180 bottom
C341  0.1UF  [CC0201]  121.98 69.52 180 bottom
C342  1UF  [CC0402_25]  143.29 69.19 180 bottom
C343  0.1UF  [CC0201]  145.4 68.81 90 bottom
C344  0.1uF  [CC0402_25]  124.26 68.76 0 bottom
C345  1UF  [CC0402_25]  140.62 68.12 90 bottom
C346  0.1UF  [CC0201]  139.81 68.02 90 bottom
C347  0.1UF  [CC0201]  144.61 67.99 90 bottom
C348  0.1UF  [CC0201]  143.8 67.99 90 bottom
C349  0.1UF  [CC0201]  143.01 67.99 90 bottom
C350  0.1UF  [CC0201]  142.22 67.99 90 bottom
C351  0.1UF  [CC0201]  141.43 67.99 90 bottom
C352  0.1UF  [CC0201]  138.99 67.99 90 bottom
C353  0.1UF  [CC0201]  138.21 67.97 90 bottom
C354  0.1UF  [CC0201]  137.39 67.97 90 bottom
C355  0.1uF  [CC0402_25]  124.26 67.74 0 bottom
C356  2.2uF  [CC0402_25]  153.63 67.49 270 bottom
C357  2.2uF  [CC0402_25]  151.69 67.49 270 bottom
C358  3000pF  [CC0603_OV]  155.2 67.41 90 bottom
C359  0.1UF  [CC0201]  145.4 67.21 270 bottom
C360  0.1UF  [CC0201]  139.38 66.82 0 bottom
C361  0.1UF  [CC0201]  144.18 66.8 180 bottom
C362  0.1UF  [CC0201]  142.6 66.8 180 bottom
C363  0.1UF  [CC0201]  141 66.8 180 bottom
C364  0.1UF  [CC0201]  137.8 66.8 0 bottom
C365  0.1uF  [CC0402_25]  124.26 66.72 180 bottom
C366  0.1uF  [CC0402_25]  129.6 66.47 180 bottom
C367  10uF  [CC0603_OV]  121.85 66.47 90 bottom
C368  10uF  [CC0603_OV]  119.82 66.47 90 bottom
C369  10uF  [CC0603_OV]  117.91 66.47 90 bottom
C370  1UF  [CC0402_25]  90.99 66.47 180 bottom
C371  0.1UF  [CC0201]  145.01 66.04 0 bottom
C372  0.1UF  [CC0201]  139.35 66.01 180 bottom
C373  0.1UF  [CC0201]  137.83 66.01 180 bottom
C374  0.1UF  [CC0201]  141.84 65.99 180 bottom
C375  0.1UF  [CC0201]  135.44 65.99 180 bottom
C376  10uF  [CC0603_OV]  109.78 65.96 180 bottom
C377  0.1uF  [CC0402_25]  124.26 65.71 180 bottom
C378  0.1UF  [CC0201]  143.8 65.61 270 bottom
C379  0.1UF  [CC0201]  143.01 65.61 90 bottom
C380  1UF  [CC0402_25]  140.57 65.45 270 bottom
C381  0.1uF  [CC0402_25]  129.6 65.45 180 bottom
C382  0.1UF  [CC0201]  136.2 65.22 0 bottom
C383  0.1UF  [CC0201]  139.35 65.2 0 bottom
C384  0.1UF  [CC0201]  137.85 65.2 0 bottom
C385  0.1UF  [CC0201]  144.99 65.17 0 bottom
C386  0.1uF  [CC0402_25]  74.61 61.39 180 top
C387  0.1UF  [CC0201]  141.41 64.82 270 bottom
C388  0.1UF  [CC0201]  142.22 64.79 90 bottom
C389  0.1UF  [CC0201]  135.41 64.49 180 bottom
C390  0.1UF  [CC0201]  136.96 64.46 180 bottom
C391  0.1uF  [CC0402_25]  129.6 64.44 0 bottom
C392  0.1UF  [CC0201]  144.99 64.41 0 bottom
C393  0.1UF  [CC0201]  143.39 64.41 180 bottom
C394  0.1UF  [CC0201]  139.45 64.39 180 bottom
C395  10uF  [CC0603_OV]  109.78 64.31 180 bottom
C396  0.1UF  [CC0201]  138.06 64.06 270 bottom
C397  1UF  [CC0402_25]  136.71 63.64 180 bottom
C398  1UF  [CC0402_25]  143.95 63.6 0 bottom
C399  1UF  [CC0402_25]  141.79 63.6 0 bottom
C400  1UF  [CC0402_25]  139.38 63.57 0 bottom
C401  2.2uF  [CC0402_25]  152 63.52 90 bottom
C402  2.2uF  [CC0402_25]  150.86 63.52 90 bottom
C403  0.1uF  [CC0402_25]  129.6 63.42 0 bottom
C404  3000pF  [CC0603_OV]  155.3 63.37 270 bottom
C405  0.1uF  [CC0402_25]  92.13 62.91 0 bottom
C406  0.1UF  [CC0201]  136.2 62.81 0 bottom
C407  0.1UF  [CC0201]  144.99 62.79 0 bottom
C408  0.1uF  [CC0402_25]  87.05 62.79 180 bottom
C409  0.1uF  [CC0402_25]  125.66 62.53 180 bottom
C410  10uF  [CC0603_OV]  123.25 62.53 270 bottom
C412  0.1UF  [CC0201]  143.82 62.41 90 bottom
C413  0.1UF  [CC0201]  141.38 62.41 270 bottom
C414  0.1UF  [CC0201]  139.81 62.41 90 bottom
C415  0.1UF  [CC0201]  138.99 62.41 270 bottom
C416  0.1UF  [CC0201]  138.21 62.41 90 bottom
C417  0.1uF  [CC0402_25]  129.6 62.41 0 bottom
C418  0.1UF  [CC0201]  143.01 62.38 270 bottom
C419  0.1UF  [CC0201]  137.42 62.38 270 bottom
C420  0.1UF  [CC0201]  142.22 62.35 90 bottom
C422  2.2uF  [CC0402_25]  121.98 62.02 90 bottom
C423  2.2uF  [CC0402_25]  120.45 62.02 90 bottom
C424  0.1UF  [CC0201]  144.99 62 0 bottom
C425  3000pF  [CC0603_OV]  118.55 61.77 270 bottom
C426  0.1UF  [CC0201]  136.2 61.59 315 bottom
C427  0.1uF  [CC0402_25]  125.66 61.52 180 bottom
C428  0.1uF  [CC0402_25]  48.82 145.08 270 bottom
C429  0.1uF  [CC0402_25]  129.6 61.26 0 bottom
C430  0.1UF  [CC0201]  143.8 60.86 270 bottom
C431  0.1UF  [CC0201]  144.61 60.83 270 bottom
C432  0.1UF  [CC0201]  143.01 60.83 270 bottom
C433  0.1UF  [CC0201]  139.78 60.83 270 bottom
C434  0.01uF  [CC0201]  142.22 60.81 270 bottom
C435  0.01uF  [CC0201]  141.41 60.81 270 bottom
C436  0.1UF  [CC0201]  137.39 60.81 270 bottom
C437  0.1UF  [CC0201]  138.21 60.78 270 bottom
C438  0.1UF  [CC0201]  138.99 60.75 270 bottom
C439  0.1uF  [CC0402_25]  48.82 122.98 90 bottom
C440  0.1uF  [CC0402_25]  48.82 133.91 270 bottom
C441  0.1UF  [CC0201]  124.77 60.37 180 bottom
C442  0.01uF  [CC0201]  135.82 59.99 90 bottom
C443  22UF  [CC0805_OV]  53.02 140.26 270 bottom
C444  0.1uF  [CC0402_25]  185.1 59.61 270 bottom
C445  0.1UF  [CC0201]  137.78 59.61 0 bottom
C446  0.1UF  [CC0201]  132.98 59.61 180 bottom
C447  0.1UF  [CC0201]  134.63 59.59 0 bottom
C449  1UF  [CC0402_25]  142.58 59.2 315 bottom
C450  3000pF  [CC0603_OV]  119.06 58.98 90 bottom
C451  2.2uF  [CC0402_25]  122.1 58.72 270 bottom
C452  2.2uF  [CC0402_25]  120.83 58.72 270 bottom
C453  0.01uF  [CC0201]  138.99 57.58 270 bottom
C454  0.1UF  [CC0201]  130.36 57.45 180 bottom
C455  1UF  [CC0603_OV]  83.75 57.07 0 bottom
C456  0.1uF  [CC0402_25]  46.92 123.49 270 bottom
C457  0.1uF  [CC0402_25]  46.92 135.56 270 bottom
C458  0.1uF  [CC0402_25]  47.05 144.45 90 bottom
C459  0.1UF  [CC0201]  138.77 55.83 315 bottom
C460  10uF  [CC0603_OV]  129.34 55.67 180 bottom
C461  0.1uF  [CC0402_25]  175.95 55.55 90 bottom
C462  10uF  [CC0603_OV]  159.31 55.04 0 bottom
C463  22UF  [CC0805_OV]  46.54 130.1 90 bottom
C464  3000pF  [CC0603_OV]  124.77 54.28 270 bottom
C465  4.7uF  [CC0603_OV]  122.87 54.28 270 bottom
C466  0.1uF  [CC0402_25]  185.1 54.15 270 bottom
C467  47UF  [CC1210]  119.69 54.15 270 bottom
C468  10uF  [CC0603_OV]  129.34 53.13 180 bottom
C469  0.1uF  [CC0402_25]  58.1 79.42 270 top
C470  10uF  [CC0603_OV]  152.2 50.85 270 bottom
C471  10uF  [CC0603_OV]  149.79 50.85 270 bottom
C472  10uF  [CC0603_OV]  146.74 50.72 270 bottom
C473  10uF  [CC0603_OV]  125.91 50.09 270 bottom
C474  0.1uF  [CC0402_25]  90.99 48.94 180 bottom
C475  0.1UF  [CC0201]  127.56 48.31 270 bottom
C476  10uF  [CC0603_OV]  155.25 47.17 270 bottom
C477  0.1uF  [CC0402_25]  57.97 82.6 270 top
C478  1UF  [CC0603_OV]  91.24 46.4 0 bottom
C479  0.1UF  [CC0201]  153.85 45.51 270 bottom
C480  1UF  [CC0603_OV]  106.99 40.31 90 bottom
C481  0.1uF  [CC0402_25]  104.2 39.67 270 bottom
C482  10uF  [CC0603_OV]  142.04 30.02 90 bottom
C483  0.1UF  [CC0201]  140.14 29.77 90 bottom
C484  0.1UF  [CC0201]  138.49 29.77 90 bottom
C485  0.1uF  [CC0402_25]  172.17 29 90 bottom
C486  0.1uF  [CC0402_25]  171.02 29 90 bottom
C487  0.1uF  [CC0402_25]  169.75 29 90 bottom
C488  0.1UF  [CC0201]  115.22 27.33 180 bottom
C489  0.1UF  [CC0201]  157.11 27.3 180 bottom
C490  0.1UF  [CC0201]  143.16 27.3 180 bottom
C491  0.1UF  [CC0201]  129.19 27.3 180 bottom
C492  0.1UF  [CC0201]  135.95 26.97 90 bottom
C493  0.1UF  [CC0201]  144.3 26.95 90 bottom
C494  0.1UF  [CC0201]  121.98 26.95 90 bottom
C495  0.1UF  [CC0201]  163.86 26.92 90 bottom
C496  0.1UF  [CC0201]  116.36 26.92 90 bottom
C497  0.1UF  [CC0201]  158.27 26.9 90 bottom
C498  0.1UF  [CC0201]  149.89 26.87 90 bottom
C499  0.1UF  [CC0201]  130.33 26.87 90 bottom
C500  0.1UF  [CC0201]  115.22 26.52 180 bottom
C501  0.1UF  [CC0201]  157.08 26.49 180 bottom
C502  0.1UF  [CC0201]  143.16 26.49 180 bottom
C503  0.1UF  [CC0201]  129.19 26.49 180 bottom
C504  0.1UF  [CC0201]  161.96 25.7 180 bottom
C505  0.1UF  [CC0201]  148.65 25.7 0 bottom
C506  0.1UF  [CC0201]  134.73 25.68 0 bottom
C507  0.1UF  [CC0201]  120.68 25.68 0 bottom
C508  0.1UF  [CC0201]  136.71 25.32 270 bottom
C509  0.1UF  [CC0201]  115.58 25.32 270 bottom
C510  0.1UF  [CC0201]  164.67 25.3 270 bottom
C511  0.1UF  [CC0201]  150.7 25.3 270 bottom
C512  0.1UF  [CC0201]  143.52 25.3 270 bottom
C513  0.1UF  [CC0201]  129.52 25.3 270 bottom
C514  0.1UF  [CC0201]  122.76 25.3 270 bottom
C515  0.1UF  [CC0201]  157.46 25.25 270 bottom
C516  0.1UF  [CC0201]  157.89 24.1 180 bottom
C517  0.1UF  [CC0201]  129.93 24.1 180 bottom
C518  0.1UF  [CC0201]  164.24 24.08 0 bottom
C519  0.1UF  [CC0201]  150.3 24.08 0 bottom
C520  0.1UF  [CC0201]  143.92 24.08 180 bottom
C521  0.1UF  [CC0201]  136.33 24.08 0 bottom
C522  0.1UF  [CC0201]  122.31 24.08 0 bottom
C523  0.1UF  [CC0201]  115.91 24.08 180 bottom
C524  1.0UF  [CC0402_25]  92.89 23.67 270 bottom
C525  0.1UF  [CC0402_25]  90.48 23.42 270 bottom
C526  0.1UF  [CC0201]  157.13 23.29 180 bottom
C527  0.1UF  [CC0201]  143.19 23.29 180 bottom
C528  0.1UF  [CC0201]  129.19 23.29 180 bottom
C529  0.1UF  [CC0201]  115.25 23.29 180 bottom
C530  0.1UF  [CC0201]  164.98 22.48 0 bottom
C531  0.1UF  [CC0201]  151.03 22.48 0 bottom
C532  0.1UF  [CC0201]  136.73 22.07 270 bottom
C533  0.1UF  [CC0201]  122.76 22.07 270 bottom
C534  1.0UF  [CC0402_25]  97.08 21.89 180 bottom
C535  0.1uF  [CC0402_25]  160.97 21.38 180 bottom
C536  0.1UF  [CC0201]  143.47 21.33 90 bottom
C537  0.1UF  [CC0201]  115.55 21.31 90 bottom
C538  0.1UF  [CC0201]  164.67 21.28 90 bottom
C539  0.1UF  [CC0201]  150.7 21.28 90 bottom
C540  0.1UF  [CC0201]  129.55 21.28 90 bottom
C541  0.1UF  [CC0201]  157.41 21.26 90 bottom
C542  0.1UF  [CC0201]  137.06 20.9 0 bottom
C543  0.1UF  [CC0201]  123.09 20.88 0 bottom
C544  4.7uF  [CC0603_OV]  101.02 20.62 0 bottom
C545  0.1UF  [CC0402_25]  97.08 20.62 180 bottom
C546  0.1UF  [CC0201]  116.36 20.55 270 bottom
C547  0.1UF  [CC0201]  144.28 20.52 270 bottom
C548  0.1UF  [CC0201]  130.33 20.52 270 bottom
C549  0.1UF  [CC0201]  158.3 20.5 270 bottom
C550  0.1UF  [CC0402_25]  89.85 20.24 0 bottom
C551  4.7uF  [CC0603_OV]  86.54 20.11 180 bottom
C552  0.1UF  [CC0201]  157.46 18.92 90 bottom
C553  0.1UF  [CC0201]  143.49 18.9 90 bottom
C554  0.1UF  [CC0201]  129.52 18.9 90 bottom
C555  0.1UF  [CC0201]  115.55 18.9 90 bottom
C556  4.7uF  [CC0603_OV]  101.02 18.84 0 bottom
C557  0.1UF  [CC0402_25]  97.08 18.84 180 bottom
C558  0.1UF  [CC0402_25]  89.59 18.72 0 bottom
C559  0.1UF  [CC0201]  164.17 18.49 0 bottom
C560  0.1UF  [CC0201]  150.25 18.49 0 bottom
C561  0.1UF  [CC0201]  136.28 18.49 0 bottom
C562  0.1UF  [CC0201]  122.31 18.49 0 bottom
C563  4.7uF  [CC0603_OV]  86.54 18.34 180 bottom
C564  1.0UF  [CC0402_25]  97.08 17.83 180 bottom
C565  1UF  [CC0402_25]  162.49 17.7 180 bottom
C566  1UF  [CC0402_25]  148.52 17.7 180 bottom
C567  1UF  [CC0402_25]  134.68 17.7 180 bottom
C568  1UF  [CC0402_25]  120.71 17.7 180 bottom
C569  10uF  [CC0603_OV]  112.83 17.7 270 bottom
C570  0.1UF  [CC0402_25]  89.59 17.45 0 bottom
C571  0.1UF  [CC0201]  164.67 17.24 90 bottom
C572  0.1UF  [CC0201]  151.03 16.91 0 bottom
C573  0.1UF  [CC0201]  137.04 16.89 0 bottom
C574  0.1UF  [CC0201]  123.09 16.89 0 bottom
C575  1UF  [CC0402_25]  148.52 16.69 180 bottom
C576  1UF  [CC0402_25]  134.68 16.69 180 bottom
C577  1UF  [CC0402_25]  120.71 16.69 180 bottom
C578  1UF  [CC0402_25]  162.49 16.56 180 bottom
C579  4.7uF  [CC0603_OV]  86.54 16.56 180 bottom
C580  1.0UF  [CC0402_25]  96.45 16.05 90 bottom
C581  0.1UF  [CC0402_25]  94.16 16.05 90 bottom
C582  0.1UF  [CC0402_25]  92.64 16.05 90 bottom
C583  1.0UF  [CC0402_25]  90.61 16.05 90 bottom
C584  1UF  [CC0402_25]  117.91 13.13 90 bottom
C585  1UF  [CC0402_25]  116.52 13.13 90 bottom
C586  1UF  [CC0402_25]  115.25 13.13 90 bottom
C587  1UF  [CC0402_25]  114.1 13.13 90 bottom
C588  1UF  [CC0402_25]  112.83 13.13 90 bottom
C589  1UF  [CC0402_25]  111.56 13.13 90 bottom
C590  4.7uF  [CC0603_OV]  90.1 13 180 bottom
C591  10uF  [CC0603_OV]  110.04 12.88 90 bottom
C592  4.7uF  [CC0603_OV]  92.64 12.88 270 bottom
C593  0.1uF  [CC0402_25]  152.08 12.62 90 bottom
C594  0.1uF  [CC0402_25]  143.57 12.62 90 bottom
C595  0.1uF  [CC0402_25]  138.99 12.62 90 bottom
C596  4.7uF  [CC0603_OV]  98.48 12.49 270 bottom
C597  4.7uF  [CC0603_OV]  96.7 12.49 270 bottom
C598  4.7uF  [CC0603_OV]  94.8 12.49 270 bottom
C599  0.1uF  [CC0402_25]  156.9 12.11 90 bottom
C600  0.1uF  [CC0402_25]  169.73 11.48 180 bottom
C601  470PF  [CC0603_OV]  135.82 10.97 90 bottom
C602  470PF  [CC0603_OV]  133.91 10.97 90 bottom
C603  100PF  [CC0603_OV]  127.82 10.97 90 bottom
C604  100PF  [CC0603_OV]  125.91 10.97 90 bottom
C605  0.1uF  [CC0402_25]  169.73 10.08 180 bottom
C606  0.1uF  [CC0402_25]  169.73 8.68 180 bottom
C607  100PF  [CC0603_OV]  112.07 7.29 180 bottom
C608  100PF  [CC0603_OV]  112.2 3.35 180 bottom
C609  0.1uF  [CC0402_25]  179.76 87.42 90 top
C611  22uF  [CC0805_OV]  101.53 53.39 0 bottom
C622  22UF  [CC0805_OV]  21.77 70.41 180 top
C623  0.1uF  [CC0402_25]  22.03 66.98 180 top
C624  0.1uF  [CC0402_25]  22.03 68.37 180 top
C626  22UF  [CC0805_OV]  60.13 139.11 180 top
C627  0.1uF  [CC0402_25]  59.11 146.73 90 top
C628  0.1uF  [CC0402_25]  60.51 146.73 90 top
C630  1UF  [CC0603_OV]  18.47 70.53 270 top
C631  2200PF  [CC0603_OV]  18.34 89.33 90 top
C632  10pF  [CC0402_25]  19.61 79.3 90 top
C633  0.1uF  [CC0402_25]  15.42 79.8 270 top
C634  47UF  [CC1210]  9.58 70.66 270 top
C635  10uF  [CC0603_OV]  12.5 89.33 90 top
C636  22uF  [CC0805_OV]  10.09 86.41 270 top
C637  0.1uF  [CC0402_25]  14.03 89.08 270 top
C638  1UF  [CC0603_OV]  16.57 78.03 270 top
C639  47UF  [CC1210]  6.41 77.52 90 top
C643  47UF  [CC1210]  14.66 70.66 270 top
C644  0.1uF  [CC0402_25]  74.61 63.42 90 top
C645  0.1uF  [CC0402_25]  77.91 88.31 270 top
C646  0.1uF  [CC0402_25]  156.77 94.03 270 bottom
C647  0.1uF  [CC0402_25]  156.77 105.46 90 top
C648  47UF  [CC1210]  49.97 85.65 0 top
C649  1UF  [CC0603_OV]  50.09 89.46 0 top
C650  2200PF  [CC0603_OV]  31.3 89.33 180 top
C651  10pF  [CC0402_25]  41.33 90.6 180 top
C652  0.1uF  [CC0402_25]  40.82 86.41 0 top
C653  47UF  [CC1210]  49.97 80.57 0 top
C654  10uF  [CC0603_OV]  31.3 83.49 180 top
C655  22uF  [CC0805_OV]  34.22 81.07 0 top
C656  0.1uF  [CC0402_25]  31.55 85.01 0 top
C657  1UF  [CC0603_OV]  42.6 87.55 0 top
C658  47UF  [CC1210]  43.36 77.39 180 top
D1  B1100-13-F  [SMA2_4_4P6X2P9]  74.73 165.15 90 top
D2  B1100-13-F  [SMA2_4_4P6X2P9]  79.18 165.15 90 top
D3  B1100-13-F  [SMA2_4_4P6X2P9]  83.62 165.15 90 top
D4  B1100-13-F  [SMA2_4_4P6X2P9]  87.94 165.15 90 top
D5  CMHD3595  [SOD123_A]  201.22 152.32 180 top
D6  MMSZ5245B  [SOD123]  64.95 141.4 0 top
D7  B1100-13-F  [SMA2_4_4P6X2P9]  87.81 116 0 bottom
D8  CMDSH-3 TR LEAD FREE  [SOD323]  205.42 109.01 0 top
D9  MBR120VLSFT1G  [SOD-123]  80.19 92.76 180 top
D10  MBR120VLSFT1G  [SOD-123]  80.19 95.43 180 top
D11  LED_GRN_DL  [LED_0603]  75.62 92.89 270 top
D12  LED GRN/YLW  [LED4_2P54_9P3X4P5MM]  116 7 90 top
D13  LED GRN/YLW  [LED4_2P54_9P3X4P5MM]  124 7 90 top
D14  LED GRN/YLW  [LED4_2P54_9P3X4P5MM]  132 7 90 top
D15  LED_GRN  [LED2_2P54_6P6X4P3MM]  167 3 90 top
D16  LED_GRN  [LED2_2P54_6P6X4P3MM]  151 3 90 top
D17  LED_GRN  [LED2_2P54_6P6X4P3MM]  143 3 90 top
D18  LED_YEL  [LED2_2P54_6P6X4P3MM]  159 3 90 top
D19  B1100-13-F  [SMA2_4_4P6X2P9]  87.94 165.15 270 bottom
D20  B1100-13-F  [SMA2_4_4P6X2P9]  83.62 165.15 270 bottom
D21  B1100-13-F  [SMA2_4_4P6X2P9]  79.18 165.15 270 bottom
D22  B1100-13-F  [SMA2_4_4P6X2P9]  74.73 165.15 270 bottom
D23  SMAJ58A  [SMA]  75.49 159.18 0 bottom
D24  BAS21  [SOT23]  74.99 145.34 180 bottom
D25  BAT54-7-F  [SOT23-40X40]  72.57 118.03 90 bottom
F1  5A  [FUSE_HOLD_10P4X3_TH]  65.08 152.07 270 top
FL1  NFM18PC225B1A3  [CC0603_NFM18PC]  116.64 61.77 270 bottom
FL2  NFM18PC225B1A3  [CC0603_NFM18PC]  116.39 58.21 180 bottom
J1  CONN PWR 1  [CON3_PWR_JACK]  65.99 159.65 180 top
J2  USB_TYPE_A_FEMALE  [USB_A_TH_SAMTEC]  200.5 158.97 180 top
J3  RJ45-19  [CON19_RJ-45_LED_80MIL_TH_RA]  146.92 152.98 0 top
J4  RJ-45  [CON_RJ45_LED_20_TH]  96.93 146.9 0 top
J5  RJ-45  [CON_RJ45_LED_20_TH]  121.93 146.9 0 top
J6  HDR 1X2  [HDR102]  210.37 152.32 90 top
J7  HDR_1X7  [JUMP1X7-6040]  179.76 145.46 0 top
J8  HDR TH 1X3  [HDR103]  177.22 120.83 180 top
J9  HDR TH 1X3  [HDR103]  140.65 102.66 90 top
J10  HDR 1X2  [HDR102]  183.57 98.6 90 top
J11  HDR 1X2  [HDR102]  186.11 94.92 270 top
J12  HDR TH 1X3  [HDR103]  84 78.66 0 top
J13  HTST-108-01-L-DV  [HDR208_HTST_SM]  196.4 43.36 270 top
J14  HDR TH 1X3  [HDR103]  89.85 31.8 90 top
J16  SD/MMC SKT  [CON_SDCARD_13F_SM_RA_511]  188.1 14.5 0 bottom
J18  HDR_1X3  [HDR1X3_50MIL]  92.89 39.55 180 top
J19  HDR_1X3  [HDR1X3_50MIL]  134.55 99.49 90 top
J20  HDR_1X3  [HDR1X3_50MIL]  209.99 130.6 270 top
J21  HDR_1X3  [HDR1X3_50MIL]  209.99 126.54 270 top
J23  HDR_1X3  [HDR1X3_50MIL]  11.74 93.39 180 top
J24  RJ45  [CON16_RJ45_LED_80_TH_RA]  146.92 152.98 180 top
J25  HDR_2X4  [HDR2X4_50MIL]  34.85 72.95 270 top
J26  HDR_1X3  [HDR1X3_50MIL]  25.71 93.39 180 top
J27  HDR_2X4  [HDR2X4_50MIL]  37.9 92.12 180 top
L1  120OHM  [IND_0603]  201.22 155.37 180 top
L2  120OHM  [IND_0603]  194.24 154.73 90 top
L3  1000OHM  [IND_0402]  184.33 154.48 0 top
L4  90OHM  [IND4_CHOKE_0805]  197.03 153.85 90 top
L5  1000OHM  [IND_0402]  184.33 153.34 0 top
L6  1000OHM  [IND_0402]  171.38 151.43 180 top
L7  1000OHM  [IND_0402]  171.38 150.29 180 top
L8  600 OHM  [IND_0805]  174.3 146.99 0 top
L9  10uH  [IND_DO1608]  71.56 142.8 270 top
L10  600OHM  [IND_0603]  141.28 139.76 90 top
L11  2.2UH  [IND2_4P3X4P3]  185.98 137.21 90 top
L12  600 OHM  [IND_0805]  173.54 136.83 0 top
L13  0.33uH  [IND_DO1813]  80.32 115.26 0 top
L14  2.2UH  [IND2_4P3X4P3]  104.58 125.53 270 top
L15  2.2UH  [IND2_4P3X4P3]  127.95 125.53 270 top
L16  1uH  [IND_DS3316]  195.38 120.44 90 top
L17  MPZ2012S101A  [IND_0805]  178.24 108.76 90 top
L18  2.2uH  [IND2_XAL50XX_222]  94.42 60.12 270 top
L19  2.2uH  [IND2_XAL50XX_222]  84.77 50.72 180 top
L20  2.2uH  [IND2_XAL50XX_222]  101.91 36.5 180 top
L21  1.5uH  [IND2_4P3SQ_XFL4020]  102.42 19.61 0 top
L22  1uH  [IND2_XAL40]  84 18.72 0 top
L23  1.5uH  [IND2_4P3SQ_XFL4020]  90.99 9.95 270 top
L24  1.5uH  [IND2_4P3SQ_XFL4020]  96.07 9.95 90 top
L25  220 OHM  [IND_0603]  88.83 83.36 0 bottom
L26  220 OHM  [IND_0603]  97.34 71.93 180 bottom
L27  120OHM  [IND_0603]  156.37 70.71 90 bottom
L28  120OHM  [IND_0603]  157.66 67.23 90 bottom
L29  120OHM  [IND_0603]  158.04 64.18 0 bottom
L30  2.2uH  [IND2_XAL50XX_222]  11.74 77.9 270 top
L31  2.2uH  [IND2_XAL50XX_222]  42.73 82.73 0 top
NOREF  -  []  68.98 154.72 90 top
NOREF#2  -  []  133.09 144.36 90 top
NOREF#3  -  []  65.98 154.72 0 top
NOREF#4  -  []  18.29 83.75 90 top
NOREF#5  -  []  91.6 140.02 0 top
NOREF#6  -  []  24.54 92.5 90 top
NOREF#7  -  []  25.71 93.39 90 top
NOREF#8  -  []  162.47 115.17 0 top
NOREF#9  -  []  133.1 141.82 90 top
NOREF#10  -  []  76.84 121 0 top
NOREF#11  -  []  194.01 134.82 0 top
NOREF#12  -  []  109.02 105.02 0 top
NOREF#13  -  []  143.11 172.92 0 top
NOREF#14  -  []  11.74 93.39 90 top
NOREF#15  -  []  158.1 150.44 90 top
NOREF#16  -  []  106.65 94.05 90 top
NOREF#17  -  []  0 0 90 top
NOREF#18  -  []  24.54 96.82 0 top
NOREF#19  -  []  172 116.06 0 top
NOREF#20  -  []  62.1 78.78 0 top
NOREF#21  -  []  145.9 150.44 90 top
NOREF#22  -  []  87.87 148.84 90 top
NOREF#23  -  []  95.46 51.1 0 top
NOREF#24  -  []  12.25 82.95 0 top
NOREF#25  -  []  150.98 152.98 0 top
NOREF#26  -  []  190.49 16.9 90 top
NOREF#27  -  []  157.08 147.9 0 top
NOREF#28  -  [unnamed#2]  61.27 3.99 0 top
NOREF#29  -  []  83.8 150.93 90 top
NOREF#30  -  []  184.7 22.01 0 top
NOREF#31  -  []  106.65 96.25 0 top
NOREF#32  -  []  14.55 86 0 top
NOREF#33  -  []  80.6 114.15 90 top
NOREF#34  -  []  -25.68 -158.29 0 top
NOREF#35  -  []  215.07 36.5 0 top
NOREF#36  -  []  33.58 72.95 0 top
NOREF#37  -  []  87.53 60.75 0 top
NOREF#38  -  []  34.58 83.23 0 top
NOREF#39  -  []  95.91 144.36 0 top
NOREF#40  -  []  150.44 120.58 0 top
NOREF#41  -  []  108.09 144.36 90 top
NOREF#42  -  []  167.43 120.58 90 top
NOREF#43  -  []  146.92 152.98 90 top
NOREF#44  -  []  178.02 88.58 90 top
NOREF#45  -  []  102.29 44.14 0 top
NOREF#46  -  []  96.41 154.02 0 top
NOREF#47  -  []  182.52 88.58 0 top
NOREF#48  -  []  167.43 136.58 90 top
NOREF#49  -  []  66.59 78.78 0 top
NOREF#50  -  []  160.69 103.17 0 top
NOREF#51  -  []  160.79 159.58 90 top
NOREF#52  -  []  91.73 38.66 90 top
NOREF#53  -  []  121.41 154.02 0 top
NOREF#54  -  []  88.97 94.86 0 top
NOREF#55  -  []  144.47 163.39 0 top
NOREF#56  -  []  30.16 70.51 90 top
NOREF#57  -  []  79.05 125.46 90 top
NOREF#58  -  []  156.79 103.17 0 top
NOREF#59  -  []  10.57 96.82 0 top
NOREF#60  -  []  197.11 134.82 90 top
NOREF#61  -  []  188.4 26.84 0 top
NOREF#62  -  []  108.1 141.82 90 top
NOREF#63  -  []  34.63 85.53 90 top
NOREF#64  -  []  206.56 125.37 0 top
NOREF#65  -  []  132.59 154.02 90 top
NOREF#66  -  []  133.35 162.14 90 top
NOREF#67  -  []  83.25 154.88 0 top
NOREF#68  -  []  95.4 48.3 90 top
NOREF#69  -  []  83.8 154.73 0 top
NOREF#70  -  []  208.72 130.6 0 top
NOREF#71  -  []  95.65 162.14 0 top
NOREF#72  -  []  83.8 154.73 0 top
NOREF#73  -  []  149.96 150.44 0 top
NOREF#74  -  []  -307.16 203.72 0 top
NOREF#75  -  []  104.59 44.09 0 top
NOREF#76  -  []  93.94 165.32 0 top
NOREF#77  -  []  -349.78 -313.18 0 top
NOREF#78  -  []  202.48 146.03 0 top
NOREF#79  -  []  144.44 125.84 0 top
NOREF#80  -  []  107.59 154.02 90 top
NOREF#81  -  []  107.59 155.48 90 top
NOREF#82  -  []  103.42 66.15 0 top
NOREF#83  -  []  156.51 97.88 90 top
NOREF#84  -  []  178.02 88.58 0 top
NOREF#85  -  []  157.08 147.9 90 top
NOREF#86  -  []  76.84 121 0 top
NOREF#87  -  []  89.33 66.79 0 top
NOREF#88  -  []  206.56 125.37 90 top
NOREF#89  -  []  92.89 39.55 90 top
NOREF#90  -  [unnamed#2]  56.19 155.62 0 top
NOREF#91  -  []  100.98 146.9 0 top
NOREF#92  -  []  188.4 22.28 90 top
NOREF#93  -  []  208.72 126.54 0 top
NOREF#94  -  []  137.4 140.02 90 top
NOREF#95  -  []  145.45 134.73 0 top
NOREF#96  -  []  35.46 91.23 90 top
NOREF#97  -  []  179.9 84.88 0 top
NOREF#98  -  []  206.56 129.44 0 top
NOREF#99  -  []  193.92 132.15 90 top
NOREF#100  -  []  144.48 165.93 0 top
NOREF#101  -  []  178.11 26.84 0 top
NOREF#102  -  []  161.34 97.08 90 top
NOREF#103  -  []  86.85 121 90 top
NOREF#104  -  []  157.66 15.54 0 top
NOREF#105  -  []  60 83.6 0 top
NOREF#106  -  []  188.4 26.18 90 top
NOREF#107  -  []  120.91 144.36 0 top
NOREF#108  -  []  108.1 141.82 90 top
NOREF#109  -  []  143.2 159.58 0 top
NOREF#110  -  []  79.37 150.11 0 top
NOREF#111  -  []  76.38 150.7 90 top
NOREF#112  -  []  88.97 87.11 0 top
NOREF#113  -  []  143.2 159.58 90 top
NOREF#114  -  []  106.34 31.86 0 top
NOREF#115  -  []  143.1 143.83 90 top
NOREF#116  -  []  143.2 159.58 90 top
NOREF#117  -  []  157.08 152.98 90 top
NOREF#118  -  []  191 132.15 90 top
NOREF#119  -  []  134.55 99.49 0 top
NOREF#120  -  []  98.56 51.1 90 top
NOREF#121  -  []  93.16 45.06 0 top
NOREF#122  -  []  12.25 82.95 90 top
NOREF#123  -  []  87.59 63.05 90 top
NOREF#124  -  []  147.17 159.58 0 top
NOREF#125  -  []  10.57 92.5 90 top
NOREF#126  -  []  108.33 41.84 90 top
NOREF#127  -  []  153.2 109.96 0 top
NOREF#128  -  []  180.21 16.9 90 top
NOREF#129  -  []  160.89 144.09 90 top
NOREF#130  -  []  132.59 155.48 90 top
NOREF#131  -  []  216 73.31 0 top
NOREF#132  -  []  37.67 83.23 90 top
NOREF#133  -  []  187.49 126.6 0 top
NOREF#134  -  []  -80.54 -95.3 270 top
NOREF#135  -  [unnamed#2]  191.38 150.42 270 top
NOREF#136  -  []  194.99 22.01 0 top
NOREF#137  -  []  148.95 156.98 90 top
NOREF#138  -  []  133.1 141.82 90 top
NOREF#139  -  []  133.66 100.66 0 top
NOREF#140  -  []  75.74 122.4 0 top
NOREF#141  -  []  62.1 78.78 90 top
NOREF#142  -  []  183.8 84.88 0 top
NOREF#143  -  []  125.99 146.9 0 top
NOREF#144  -  []  226.67 170 0 top
NOREF#145  -  []  143.2 159.58 90 top
NOREF#146  -  []  178.11 26.18 90 top
NOREF#147  -  []  120.91 141.82 0 top
NOREF#148  -  []  172 108.31 0 top
NOREF#149  -  []  137.98 98.32 90 top
NOREF#150  -  []  143.1 143.83 90 top
NOREF#151  -  []  60 82.95 90 top
NOREF#152  -  []  120.65 162.14 0 top
NOREF#153  -  []  81.76 -108.2 0 top
NOREF#154  -  []  118.94 165.32 0 top
NOREF#155  -  []  206.56 129.44 90 top
NOREF#156  -  []  91.73 42.97 0 top
NOREF#157  -  [unnamed#2]  209.54 14.15 270 top
NOREF#158  -  []  184.45 84.88 90 top
NOREF#159  -  []  37.9 92.12 90 top
NOREF#160  -  []  35.46 96.82 0 top
NOREF#161  -  []  156.51 102.37 0 top
NOREF#162  -  []  108.35 162.14 90 top
NOREF#163  -  []  112.4 140.02 90 top
NOREF#164  -  []  70.29 122.6 90 top
NOREF#165  -  []  60 79.05 90 top
NOREF#166  -  []  178.11 22.28 90 top
NOREF#167  -  []  149.43 119.58 0 top
NOREF#168  -  []  190.49 22.01 0 top
NOREF#169  -  []  150.44 120.58 0 top
NOREF#170  -  []  83.25 154.88 90 top
NOREF#171  -  []  143.1 172.91 0 top
NOREF#172  -  []  36.37 89.27 0 top
NOREF#173  -  []  0 170 0 top
NOREF#174  -  []  84.37 45.07 0 top
NOREF#175  -  []  116.6 140.02 0 top
NOREF#176  -  []  160.89 144.09 90 top
NOREF#177  -  []  142.8 54.91 0 top
NOREF#178  -  []  30.16 70.51 0 top
NOREF#179  -  []  187.49 118.98 0 top
NOREF#180  -  []  156.51 97.88 0 top
NOREF#181  -  []  168.43 119.58 90 top
NOREF#182  -  []  105.39 44.14 90 top
NOREF#183  -  []  95.9 141.82 0 top
NOREF#184  -  []  76.51 132.19 0 top
NOREF#185  -  []  180.21 22.01 0 top
NOREF#186  -  []  90.63 60.75 90 top
NOREF#187  -  []  209.61 34.59 90 bottom
NOREF#188  -  []  59.75 97.58 180 bottom
NOREF#189  -  []  121.85 116 180 bottom
NOREF#190  -  []  178.75 110.26 180 bottom
NOREF#191  -  []  165.92 99.87 180 bottom
NOREF#192  -  []  121.72 94.54 180 bottom
NOREF#193  -  [unnamed#2]  209.54 14.15 90 bottom
NOREF#194  -  [unnamed#2]  191.38 150.42 90 bottom
NOREF#195  -  []  59.37 107.74 180 bottom
NOREF#196  -  [unnamed#2]  61.27 3.99 180 bottom
NOREF#197  -  [unnamed#2]  56.19 155.62 180 bottom
NOREF#198  -  []  121.6 106.6 180 bottom
P1  RJ45  [CON8_RJ45_1P02_16X17]  173.43 164.93 180 top
P2  CON 2X26 MINI PCI EXPRESS  [CON_2X26_0P8_SMT]  36.55 59.73 0 top
P3  CON 2X26 MINI PCI EXPRESS  [CON_2X26_0P8_SMT]  52 133.78 270 top
Q1  MMBT4401L  [SOT23]  211.89 146.48 0 top
Q2  FDS2582  [SO8_1P27_4X5]  85.65 142.92 180 top
Q3  FDS3572  [SO8]  86.8 120.95 0 bottom
Q4  FDD4243  [TO252AA]  94.67 113.46 90 top
